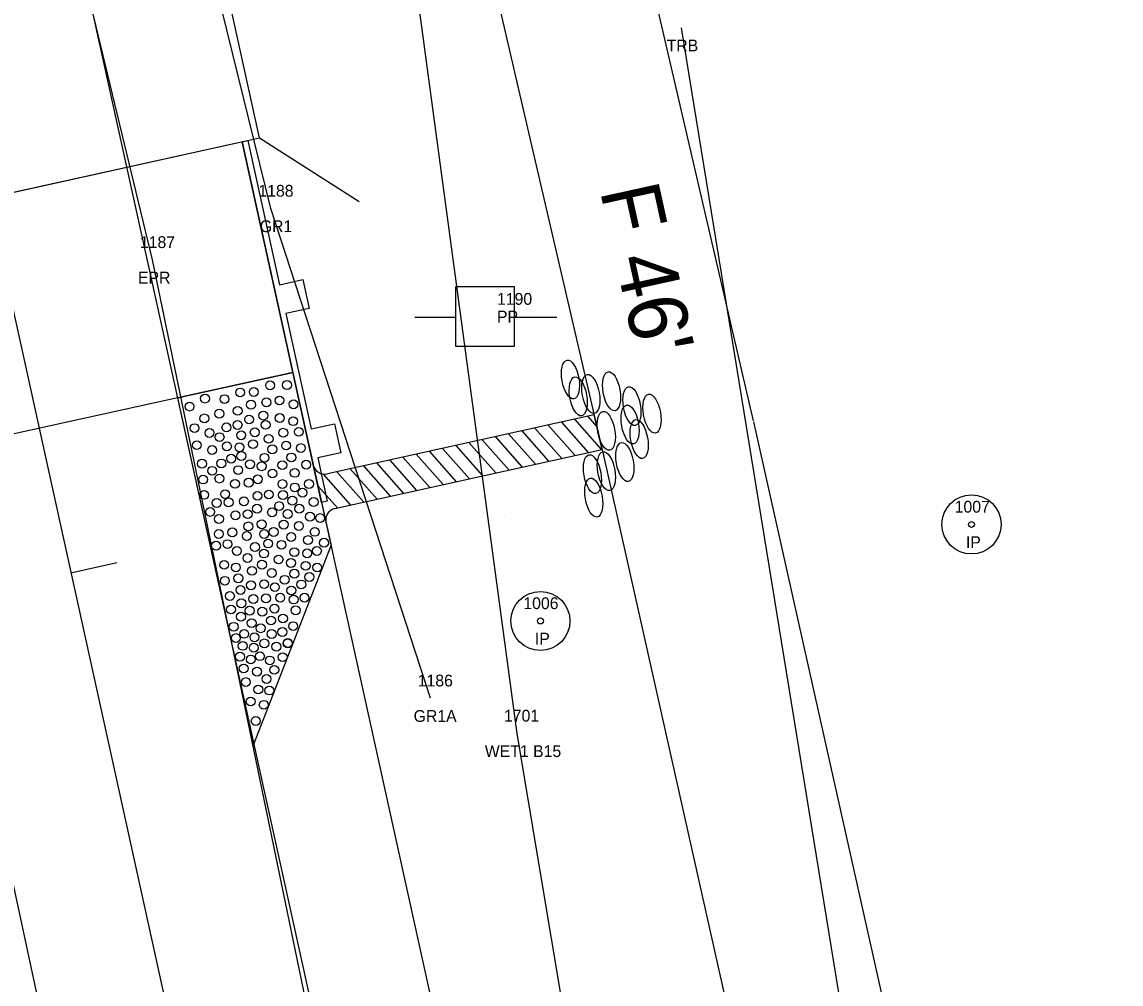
# Model space of a CAD drawing. Extents: x 2521558 to 2524785, y 882711 to 887632.
# Drawn here: x 2523806.5 to 2523899.5, y 884989.6 to 885071.1 of the extents above; entities that cross this region are included whole.
import ezdxf

# ---------------------------------------------------------------- set-up
doc = ezdxf.new("R2010")
doc.units = 0
for name, color, linetype in [('RD_EV_JW', 7, 'Continuous'), ('RD_EX_DV_Prop_txCode', 7, 'Continuous'), ('RD_EX_DV_PropPin', 7, 'Continuous'), ('RD_EX_GuardRail', 7, 'Continuous'), ('RD_EX_GuardRail_txCode', 7, 'Continuous'), ('RD_EX_H2O_WetLd_txCode', 7, 'Continuous'), ('RD_EX_Road', 7, 'Continuous'), ('RD_EX_Road_txCode', 7, 'Continuous'), ('RD_EX_UT', 7, 'Continuous'), ('RD_EX_UT_txCode', 7, 'Continuous'), ('RD_EX_VEG', 7, 'Continuous'), ('RD_EX_VEG_txCode', 7, 'Continuous'), ('RD_HC_Cl', 7, 'Continuous'), ('RD_HC_Data_Tic', 7, 'Continuous'), ('RD_PD_Bridge', 7, 'Continuous'), ('RD_PD_CstnLmt', 7, 'Continuous'), ('RD_PD_DR_ErosCtrl', 7, 'Continuous'), ('RD_PD_Final_TrvlWay', 7, 'Continuous'), ('RD_PD_GR', 7, 'Continuous'), ('RD_PD_PaveShd', 7, 'Continuous'), ('RD_PD_TX_CstnLmt', 7, 'Continuous'), ('RD_SMD_Locator', 7, 'Continuous')]:
    doc.layers.add(name, color=color, linetype=linetype)

# ---------------------------------------------------------------- blocks, each defined once
blk = doc.blocks.new('TBC1')
at = {"layer": 'RD_PD_GR'}
blk.add_lwpolyline([(12.5, 2.5), (15, 2.5), (15, 0.492), (25, 0.492), (25, 2.5), (27.5, 2.5), (27.5, 0.492), (31.25, 0.492), (31.25, 0), (0, 0), (0, 0.492), (12.5, 0.492)], close=True, dxfattribs=at)

msp = doc.modelspace()

# ---------------------------------------------------------------- linework, layer by layer
at = {"layer": 'RD_EV_JW'}
msp.add_lwpolyline([(2523944.864, 884550.08), (2523910.413, 884709.577), (2523888.007, 884815.03), (2523863.93, 884918.366), (2523848.427, 885010.841), (2523837.066, 885095.132), (2523817.825, 885104.474)], dxfattribs=at)
at = {"layer": 'RD_EX_DV_PropPin'}
for centre, radius in [((2523886.89, 885028.524), 2.499), ((2523886.89, 885028.524), 0.25), ((2523850.412, 885020.357), 2.499), ((2523850.412, 885020.358), 0.25)]:
    msp.add_circle(centre, radius, dxfattribs=at)
at = {"layer": 'RD_EX_GuardRail'}
msp.add_lwpolyline([(2523841.112, 885013.814), (2523827.604, 885055.265), (2523819.275, 885089.086)], dxfattribs=at)
at = {"layer": 'RD_EX_Road'}
for p, q in [((2523817.578, 885050.917), (2523809.375, 885084.881)), ((2523837.97, 884952.456), (2523817.578, 885050.917)), ((2523816.996, 884946.299), (2523795.465, 885045.906))]:
    msp.add_line(p, q, dxfattribs=at)
at = {"layer": 'RD_EX_UT'}
for p, q in [((2523848.225, 885048.623), (2523843.225, 885048.623)), ((2523843.225, 885048.623), (2523843.225, 885043.623)), ((2523848.225, 885043.623), (2523848.225, 885048.623)), ((2523839.793, 885046.061), (2523843.263, 885046.061)), ((2523848.153, 885046.061), (2523851.793, 885046.061)), ((2523843.225, 885043.623), (2523848.225, 885043.623))]:
    msp.add_line(p, q, dxfattribs=at)
at = {"layer": 'RD_EX_VEG'}
msp.add_lwpolyline([(2523998.747, 884575.964), (2523966.166, 884559.061), (2523924.929, 884771.448), (2523880.333, 884960.159), (2523862.357, 885070.557)], dxfattribs=at)
at = {"layer": 'RD_HC_Cl'}
msp.add_line((2523641.165, 885794.201), (2524197.759, 883266.557), dxfattribs=at)
at = {"layer": 'RD_HC_Data_Tic'}
msp.add_line((2523810.669, 885024.44), (2523814.575, 885025.3), dxfattribs=at)
at = {"layer": 'RD_PD_Bridge'}
for p, q in [((2523780.729, 885051.128), (2523826.629, 885061.235)), ((2523826.629, 885061.235), (2523835.056, 885055.85)), ((2523825.164, 885060.913), (2523829.465, 885041.381)), ((2523829.465, 885041.381), (2523786.495, 885031.918))]:
    msp.add_line(p, q, dxfattribs=at)
for points in [[(2523826.629, 885061.235), (2523798.673, 885188.194)], [(2523780.729, 885051.128), (2523826.629, 885061.235)]]:
    msp.add_lwpolyline(points, dxfattribs=at)
at = {"layer": 'RD_PD_CstnLmt'}
for p, q in [((2523844.918, 885081.017), (2523855.75, 885034.367)), ((2523855.75, 885034.367), (2523877.606, 884936.783))]:
    msp.add_line(p, q, dxfattribs=at)
at = {"layer": 'RD_PD_DR_ErosCtrl'}
for p, q in [((2523857.581, 885083.957), (2523868.413, 885037.307)), ((2523868.436, 885037.208), (2523890.291, 884939.625))]:
    msp.add_line(p, q, dxfattribs=at)
at = {"layer": 'RD_PD_Final_TrvlWay'}
msp.add_line((2523741.744, 885393.246), (2524015.933, 884148.078), dxfattribs=at)
at = {"layer": 'RD_PD_GR'}
msp.add_line((2523831.885, 885030.394), (2523990.484, 884310.149), dxfattribs=at)
at = {"layer": 'RD_PD_PaveShd'}
for p, q in [((2523819.699, 885039.23), (2523829.465, 885041.381)), ((2523829.465, 885041.381), (2523831.401, 885032.591)), ((2523819.699, 885039.23), (2523826.151, 885009.932)), ((2523854.955, 885037.791), (2523832.378, 885032.807)), ((2523852.18, 885037.178), (2523854.454, 885034.608)), ((2523852.18, 885037.178), (2523854.454, 885034.608)), ((2523853.297, 885037.425), (2523855.571, 885034.854)), ((2523853.297, 885037.425), (2523855.571, 885034.854)), ((2523854.415, 885037.671), (2523855.185, 885036.8)), ((2523855.634, 885034.868), (2523854.955, 885037.791)), ((2523847.712, 885036.192), (2523849.986, 885033.622)), ((2523847.712, 885036.192), (2523849.986, 885033.622)), ((2523848.829, 885036.438), (2523851.103, 885033.868)), ((2523848.829, 885036.438), (2523851.103, 885033.868)), ((2523849.946, 885036.685), (2523852.22, 885034.115)), ((2523849.946, 885036.685), (2523852.22, 885034.115)), ((2523851.063, 885036.932), (2523853.337, 885034.361)), ((2523851.063, 885036.932), (2523853.337, 885034.361)), ((2523843.244, 885035.206), (2523845.518, 885032.635)), ((2523843.244, 885035.206), (2523845.518, 885032.635)), ((2523844.361, 885035.452), (2523846.635, 885032.882)), ((2523844.361, 885035.452), (2523846.635, 885032.882)), ((2523845.478, 885035.699), (2523847.752, 885033.128)), ((2523845.478, 885035.699), (2523847.752, 885033.128)), ((2523846.595, 885035.945), (2523848.589, 885033.692)), ((2523846.595, 885035.945), (2523848.869, 885033.375)), ((2523833.022, 885029.877), (2523855.634, 885034.868)), ((2523838.776, 885034.219), (2523841.05, 885031.649)), ((2523838.776, 885034.219), (2523841.05, 885031.649)), ((2523839.893, 885034.466), (2523842.167, 885031.896)), ((2523839.893, 885034.466), (2523842.167, 885031.896)), ((2523841.01, 885034.712), (2523843.284, 885032.142)), ((2523841.01, 885034.712), (2523843.284, 885032.142)), ((2523842.127, 885034.959), (2523844.401, 885032.389)), ((2523842.127, 885034.959), (2523844.401, 885032.389)), ((2523835.425, 885033.48), (2523837.699, 885030.909)), ((2523835.425, 885033.48), (2523837.699, 885030.909)), ((2523836.542, 885033.726), (2523838.816, 885031.156)), ((2523837.659, 885033.973), (2523839.933, 885031.402)), ((2523837.659, 885033.973), (2523839.933, 885031.402)), ((2523831.401, 885032.591), (2523832.046, 885029.661)), ((2523832.027, 885032.793), (2523834.348, 885030.17)), ((2523833.191, 885032.986), (2523835.465, 885030.416)), ((2523833.191, 885032.986), (2523835.465, 885030.416)), ((2523834.308, 885033.233), (2523836.582, 885030.663)), ((2523834.308, 885033.233), (2523836.582, 885030.663)), ((2523831.577, 885031.792), (2523833.231, 885029.923)), ((2523832.046, 885029.661), (2523832.691, 885026.732)), ((2523826.151, 885009.932), (2523832.691, 885026.732))]:
    msp.add_line(p, q, dxfattribs=at)
for centre in [(2523828.967, 885040.325), (2523828.967, 885040.325), (2523828.967, 885040.325), (2523824.999, 885039.698), (2523824.999, 885039.698), (2523826.153, 885039.739), (2523826.153, 885039.739), (2523827.534, 885040.3), (2523827.534, 885040.3), (2523820.715, 885038.501), (2523820.715, 885038.501), (2523822.02, 885039.178), (2523822.02, 885039.178), (2523823.673, 885039.133), (2523823.673, 885039.133), (2523825.918, 885038.659), (2523825.918, 885038.659), (2523827.222, 885038.86), (2523827.222, 885038.86), (2523828.326, 885039.017), (2523828.326, 885039.017), (2523829.513, 885038.692), (2523829.513, 885038.692), (2523823.233, 885037.898), (2523823.233, 885037.898), (2523824.791, 885038.139), (2523824.791, 885038.139), (2523826.962, 885037.739), (2523826.962, 885037.739), (2523828.347, 885037.529), (2523828.347, 885037.529), (2523821.137, 885036.679), (2523821.137, 885036.679), (2523821.973, 885037.498), (2523821.973, 885037.498), (2523823.836, 885036.738), (2523823.836, 885036.738), (2523824.78, 885036.947), (2523824.78, 885036.947), (2523825.757, 885037.407), (2523825.757, 885037.407), (2523827.161, 885036.956), (2523827.161, 885036.956), (2523829.482, 885037.263), (2523829.482, 885037.263), (2523822.403, 885036.265), (2523822.403, 885036.265), (2523823.257, 885035.918), (2523823.257, 885035.918), (2523825.086, 885036.073), (2523825.086, 885036.073), (2523826.234, 885036.326), (2523826.234, 885036.326), (2523827.408, 885035.773), (2523827.408, 885035.773), (2523828.647, 885036.286), (2523828.647, 885036.286), (2523829.96, 885036.364), (2523829.96, 885036.364), (2523821.33, 885035.236), (2523821.33, 885035.236), (2523822.624, 885034.82), (2523822.624, 885034.82), (2523823.878, 885035.137), (2523823.878, 885035.137), (2523824.938, 885035.058), (2523826.089, 885035.32), (2523826.089, 885035.32), (2523827.719, 885034.884), (2523827.719, 885034.884), (2523828.889, 885035.205), (2523828.889, 885035.205), (2523830.139, 885034.988), (2523830.139, 885034.988), (2523824.24, 885034.09), (2523824.24, 885034.09), (2523825.101, 885034.315), (2523825.101, 885034.315), (2523827.057, 885034.167), (2523827.057, 885034.167), (2523829.333, 885034.196), (2523829.333, 885034.196), (2523821.767, 885033.666), (2523821.767, 885033.666), (2523822.633, 885033.066), (2523822.633, 885033.066), (2523823.407, 885033.689), (2523823.407, 885033.689), (2523824.832, 885033.125), (2523824.832, 885033.125), (2523825.83, 885033.62), (2523825.83, 885033.62), (2523826.817, 885033.452), (2523826.817, 885033.452), (2523828.563, 885033.542), (2523828.563, 885033.542), (2523829.618, 885032.888), (2523829.618, 885032.888), (2523830.587, 885033.586), (2523830.587, 885033.586), (2523821.864, 885032.324), (2523821.864, 885032.324), (2523823.244, 885032.408), (2523823.244, 885032.408), (2523824.564, 885031.963), (2523824.564, 885031.963), (2523825.721, 885032.06), (2523825.721, 885032.06), (2523826.497, 885032.349), (2523826.497, 885032.349), (2523827.734, 885032.835), (2523827.734, 885032.835), (2523828.577, 885031.941), (2523828.577, 885031.941), (2523830.823, 885031.944), (2523830.823, 885031.944), (2523821.953, 885031.028), (2523821.953, 885031.028), (2523823.725, 885031.088), (2523823.725, 885031.088), (2523827.428, 885031.058), (2523827.428, 885031.058), (2523828.627, 885031.016), (2523828.627, 885031.016), (2523829.621, 885031.656), (2523829.621, 885031.656), (2523830.274, 885031.22), (2523830.274, 885031.22), (2523823.006, 885030.346), (2523823.006, 885030.346), (2523824.02, 885030.397), (2523824.02, 885030.397), (2523825.316, 885030.486), (2523825.316, 885030.486), (2523826.467, 885030.948), (2523826.467, 885030.948), (2523828.295, 885030.079), (2523828.295, 885030.079), (2523829.418, 885030.543), (2523829.418, 885030.543), (2523831.214, 885030.426), (2523831.214, 885030.426), (2523822.459, 885029.586), (2523824.598, 885029.295), (2523824.598, 885029.295), (2523825.639, 885029.394), (2523825.639, 885029.394), (2523826.429, 885029.856), (2523826.429, 885029.856), (2523827.701, 885029.554), (2523827.701, 885029.554), (2523829.019, 885029.41), (2523829.019, 885029.41), (2523830.001, 885029.855), (2523830.001, 885029.855), (2523830.914, 885029.182), (2523830.914, 885029.182), (2523823.203, 885028.987), (2523823.203, 885028.987), (2523825.691, 885028.358), (2523825.691, 885028.358), (2523826.825, 885028.541), (2523826.825, 885028.541), (2523828.676, 885028.512), (2523828.676, 885028.512), (2523829.968, 885028.398), (2523829.968, 885028.398), (2523831.766, 885029.063), (2523831.766, 885029.063), (2523823.189, 885027.719), (2523823.189, 885027.719), (2523824.341, 885027.852), (2523824.341, 885027.852), (2523825.558, 885027.553), (2523825.558, 885027.553), (2523827.027, 885027.715), (2523827.027, 885027.715), (2523827.831, 885027.884), (2523827.831, 885027.884), (2523829.314, 885027.463), (2523829.314, 885027.463), (2523831.312, 885027.895), (2523831.312, 885027.895), (2523822.96, 885026.723), (2523822.96, 885026.723), (2523823.922, 885026.86), (2523823.922, 885026.86), (2523826.258, 885026.612), (2523826.258, 885026.612), (2523827.371, 885026.909), (2523827.371, 885026.909), (2523828.495, 885026.805), (2523828.495, 885026.805), (2523830.736, 885027.201), (2523830.736, 885027.201), (2523832.098, 885026.977), (2523832.098, 885026.977), (2523832.098, 885026.977), (2523824.722, 885026.285), (2523824.722, 885026.285), (2523825.619, 885025.69), (2523825.619, 885025.69), (2523827.01, 885026.061), (2523827.01, 885026.061), (2523828.25, 885025.557), (2523828.25, 885025.557), (2523829.579, 885026.177), (2523829.579, 885026.177), (2523830.668, 885026.083), (2523830.668, 885026.083), (2523831.494, 885026.285), (2523831.494, 885026.285), (2523823.647, 885025.109), (2523823.647, 885025.109), (2523824.637, 885024.887), (2523824.637, 885024.887), (2523826.002, 885024.601), (2523826.002, 885024.601), (2523826.84, 885025.117), (2523826.84, 885025.117), (2523829.299, 885025.269), (2523829.299, 885025.269), (2523830.547, 885025.024), (2523830.547, 885025.024), (2523831.521, 885024.88), (2523831.521, 885024.88), (2523823.705, 885023.759), (2523823.705, 885023.759), (2523824.84, 885023.97), (2523824.84, 885023.97), (2523827.675, 885024.414), (2523827.675, 885024.414), (2523828.762, 885023.842), (2523828.762, 885023.842), (2523829.58, 885024.354), (2523829.58, 885024.354), (2523830.854, 885024.079), (2523830.854, 885024.079), (2523825.026, 885022.984), (2523825.026, 885022.984), (2523825.92, 885023.378), (2523825.92, 885023.378), (2523827.027, 885023.472), (2523827.027, 885023.472), (2523827.938, 885023.219), (2523827.938, 885023.219), (2523829.325, 885022.938), (2523829.325, 885022.938), (2523830.17, 885023.448), (2523830.17, 885023.448), (2523824.131, 885022.47), (2523824.131, 885022.47), (2523825.102, 885021.848), (2523825.102, 885021.848), (2523826.119, 885022.219), (2523826.119, 885022.219), (2523827.181, 885022.266), (2523827.181, 885022.266), (2523828.389, 885022.322), (2523828.389, 885022.322), (2523829.53, 885022.168), (2523829.53, 885022.168), (2523830.44, 885022.322), (2523830.449, 885022.329), (2523824.22, 885021.325), (2523824.22, 885021.325), (2523825.799, 885021.225), (2523825.799, 885021.225), (2523826.869, 885021.144), (2523826.869, 885021.144), (2523827.898, 885021.404), (2523827.898, 885021.404), (2523829.699, 885021.26), (2523829.699, 885021.26), (2523824.449, 885019.865), (2523824.449, 885019.865), (2523825.063, 885020.725), (2523825.063, 885020.725), (2523825.975, 885020.172), (2523825.975, 885020.172), (2523827.612, 885020.396), (2523827.612, 885020.396), (2523828.618, 885020.568), (2523828.618, 885020.568), (2523829.483, 885019.92), (2523829.483, 885019.92), (2523825.343, 885019.265), (2523825.343, 885019.265), (2523826.207, 885018.972), (2523826.207, 885018.972), (2523826.735, 885019.741), (2523826.735, 885019.741), (2523827.668, 885019.251), (2523827.668, 885019.251), (2523828.563, 885019.424), (2523828.563, 885019.424), (2523824.631, 885018.908), (2523824.631, 885018.908), (2523825.216, 885018.247), (2523825.216, 885018.247), (2523826.153, 885018.093), (2523826.153, 885018.093), (2523827.041, 885018.456), (2523827.041, 885018.456), (2523828.067, 885018.184), (2523828.067, 885018.184), (2523829.025, 885018.456), (2523829.036, 885018.488), (2523824.984, 885017.331), (2523824.984, 885017.331), (2523825.9, 885017.099), (2523825.9, 885017.099), (2523826.67, 885017.372), (2523826.67, 885017.372), (2523828.589, 885017.293), (2523828.589, 885017.293), (2523825.292, 885016.334), (2523825.292, 885016.334), (2523827.515, 885017.016), (2523827.515, 885017.016), (2523827.885, 885016.22), (2523826.43, 885016.072), (2523826.43, 885016.072), (2523827.226, 885015.446), (2523827.226, 885015.446), (2523825.478, 885015.184), (2523825.478, 885015.184), (2523826.53, 885014.559), (2523826.53, 885014.559), (2523827.471, 885014.469), (2523827.471, 885014.469), (2523825.89, 885013.54), (2523825.89, 885013.54), (2523826.996, 885013.264), (2523826.996, 885013.264), (2523826.319, 885011.894)]:
    msp.add_circle(centre, 0.375, dxfattribs=at)
for centre, start, end in [((2523832.162, 885033.783), 192.41848, 282.4481), ((2523833.238, 885028.9), 102.4481, 192.41848)]:
    msp.add_arc(centre, 1, start, end, dxfattribs=at)
for centre in [(2523852.952, 885040.795), (2523852.952, 885040.795), (2523853.606, 885039.366), (2523853.606, 885039.366), (2523854.674, 885039.568), (2523854.674, 885039.568), (2523856.429, 885039.797), (2523856.429, 885039.797), (2523858.15, 885038.541), (2523858.15, 885038.541), (2523859.852, 885037.904), (2523859.852, 885037.904), (2523855.985, 885036.451), (2523855.985, 885036.451), (2523857.998, 885036.979), (2523857.998, 885036.979), (2523858.766, 885035.754), (2523858.766, 885035.754), (2523857.551, 885033.808), (2523857.551, 885033.808), (2523854.808, 885032.783), (2523855.988, 885033.034), (2523855.988, 885033.034), (2523854.924, 885030.798)]:
    msp.add_ellipse(centre, major_axis=(0.292, -1.645), ratio=0.429445, dxfattribs=at)
at = {"layer": 'RD_SMD_Locator'}
for centre in [(2523862.357, 885070.557), (2523827.604, 885055.265), (2523817.578, 885050.917), (2523847.391, 885029.225), (2523841.112, 885013.814), (2523848.427, 885010.841)]:
    msp.add_circle(centre, 0.001, dxfattribs=at)

# ---------------------------------------------------------------- block references
at = {"layer": 'RD_PD_Bridge', "rotation": -77.58151740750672}
msp.add_blockref('TBC1', (2523825.164, 885060.913), dxfattribs=at)

# ---------------------------------------------------------------- texts
at = {"layer": 'RD_EX_DV_Prop_txCode'}
for s, p in [('1007', (2523885.465, 885029.524)), ('IP', (2523886.418, 885026.524)), ('1006', (2523848.964, 885021.358)), ('IP', (2523849.94, 885018.358))]:
    msp.add_text(s, height=1, dxfattribs=at).set_placement(p)
at = {"layer": 'RD_EX_GuardRail_txCode'}
for s, p in [('1188', (2523826.541, 885056.265)), ('GR1', (2523826.659, 885053.265)), ('1186', (2523840.026, 885014.814)), ('GR1A', (2523839.679, 885011.814))]:
    msp.add_text(s, height=1, dxfattribs=at).set_placement(p)
at = {"layer": 'RD_EX_H2O_WetLd_txCode'}
for s, p in [('1701', (2523847.325, 885011.841)), ('WET1 B15', (2523845.703, 885008.841))]:
    msp.add_text(s, height=1, dxfattribs=at).set_placement(p)
at = {"layer": 'RD_EX_Road_txCode'}
for s, p in [('1187', (2523816.515, 885051.917)), ('EPR', (2523816.35, 885048.917))]:
    msp.add_text(s, height=1, dxfattribs=at).set_placement(p)
at = {"layer": 'RD_EX_UT_txCode'}
for s, p in [('1190', (2523846.734, 885047.114)), ('PP', (2523846.734, 885045.614))]:
    msp.add_text(s, height=1, dxfattribs=at).set_placement(p)
at = {"layer": 'RD_EX_VEG_txCode'}
msp.add_text('TRB', height=1, dxfattribs=at).set_placement((2523861.09, 885068.557))
at = {"layer": 'RD_PD_TX_CstnLmt'}
msp.add_text("F 46'", height=5, rotation=282.41848, dxfattribs=at).set_placement((2523855.435, 885056.801))

doc.saveas('drawing.dxf')
